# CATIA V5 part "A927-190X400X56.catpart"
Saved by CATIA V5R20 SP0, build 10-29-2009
Part number: A927-190X400X56
Source: Unknown
Property "A": "90.000"
Property "ARTICLENO": "A927-190X400X56"
Property "BOMINFO": "A927-190X400X56"
Property "CODE": "A927-190X400X56"
Property "CREATOR": "CADENAS GmbH"
Property "D": "22.000"
Property "D1": "33.000"
Property "F": "36.000"
Property "FORM": "B"
Property "L": "400.000"
Property "L1": "150.000"
Property "L2": "40.000"
Property "L3": "80.000"
Property "LINA": "A927-190X400X56"
Property "NB": "A927-190X400X56"
Property "NBSYN": "$CODE."
Property "NN": "A927"
Property "NT": "VDI 3387 Removable Die Heels, steel and self-lubricating"
Property "R": "31.500"
Property "S": "56.000"
Property "SUPPLIER": "CF"
Property "T": "25.500"
Property "W": "190.000"
Bounding box of the stored display mesh (mm): x -95 to 95, y 0 to 400, z -56 to 0
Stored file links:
  C:\Users\borellobunino\Desktop\3D X SITO CF\A927\GSB_OILLESS_G2290519040056\CATIAV5\A927-190X400X56.catpart
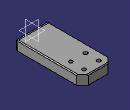
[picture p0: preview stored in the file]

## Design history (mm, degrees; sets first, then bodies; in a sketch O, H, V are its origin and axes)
Body1 "Geometry.1" (main body)
  Solid1 "A927-190X400X56.catpart": solid without history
